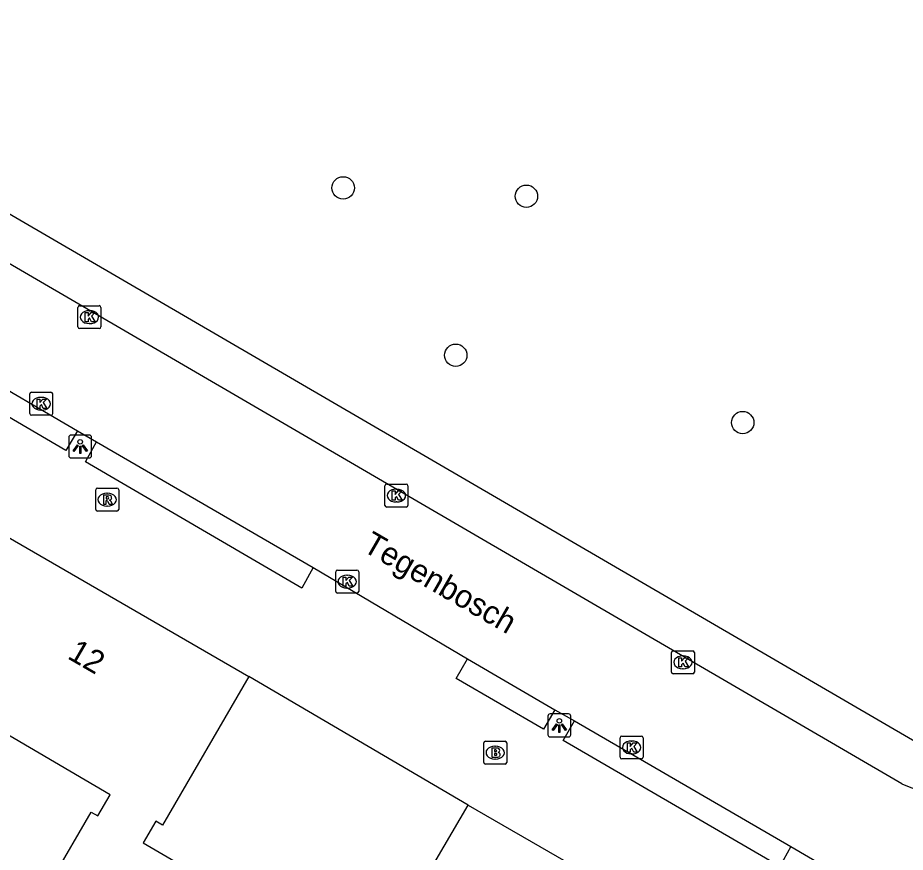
# Model space of a CAD drawing. Extents: x 156502 to 159074, y 384229 to 386094.
# Drawn here: x 157135.98 to 157174.65, y 385827.46 to 385863.84 of the extents above; entities that cross this region are included whole.
import ezdxf

# ---------------------------------------------------------------- set-up
doc = ezdxf.new("R2010")
doc.units = 0
for name, color, linetype in [('IMGEO_Boom', 7, 'Continuous'), ('IMGEO_Brandkraan', 7, 'Continuous'), ('IMGEO_Hek', 7, 'Continuous'), ('IMGEO_Kolk', 7, 'Continuous'), ('IMGEO_Lichtpunt', 7, 'Continuous'), ('IMGEO_Openbare_ruimte_label', 7, 'Continuous'), ('IMGEO_Pand', 7, 'Continuous'), ('IMGEO_Pand_nummerreeks', 7, 'Continuous'), ('IMGEO_Parkeervlak_open', 7, 'Continuous'), ('IMGEO_Rijbaan_lokaal_open', 7, 'Continuous'), ('IMGEO_Rioolput', 7, 'Continuous'), ('IMGEO_Voetpad_open', 7, 'Continuous')]:
    doc.layers.add(name, color=color, linetype=linetype)

msp = doc.modelspace()

# ---------------------------------------------------------------- linework, layer by layer
at = {"layer": 'IMGEO_Boom'}
for centre in [(157150.156, 385856.417), (157158.138, 385856.053), (157155.059, 385849.123), (157167.563, 385846.188)]:
    msp.add_circle(centre, 0.489, dxfattribs=at)
at = {"layer": 'IMGEO_Brandkraan'}
for p, q in [((157156.28, 385831.377), (157156.28, 385832.229)), ((157156.355, 385832.303), (157157.207, 385832.303)), ((157156.768, 385832.083), (157156.793, 385832.083)), ((157157.281, 385832.229), (157157.281, 385831.377)), ((157157.207, 385831.303), (157156.355, 385831.303)), ((157156.791, 385831.523), (157156.766, 385831.523))]:
    msp.add_line(p, q, dxfattribs=at)
for points in [[(157156.28, 385831.377), (157156.28, 385832.229)], [(157156.355, 385832.303), (157157.207, 385832.303)], [(157156.628, 385832.003), (157156.628, 385831.603), (157156.841, 385831.603)], [(157156.859, 385832.003), (157156.628, 385832.003)], [(157157.281, 385832.229), (157157.281, 385831.377)], [(157156.807, 385831.922), (157156.753, 385831.922), (157156.753, 385831.846)], [(157156.753, 385831.846), (157156.806, 385831.846)], [(157156.815, 385831.77), (157156.753, 385831.77), (157156.753, 385831.689)], [(157156.753, 385831.689), (157156.815, 385831.689)], [(157157.207, 385831.303), (157156.355, 385831.303)]]:
    msp.add_lwpolyline(points, dxfattribs=at)
for centre, radius, start, end in [((157156.357, 385832.227), 0.0765, 91.552, 178.448), ((157156.357, 385832.227), 0.0765, 91.552, 178.448), ((157156.863, 385831.858), 0.145, 59.4692, 91.5367), ((157157.205, 385832.227), 0.0765, 1.552, 88.448), ((157157.205, 385832.227), 0.0765, 1.552, 88.448), ((157156.808, 385831.884), 0.0379, 267.8285, 90.9355), ((157156.816, 385831.729), 0.0404, 269.8759, 90.5077), ((157156.847, 385831.854), 0.251, 268.6676, 293.5347), ((157156.888, 385831.905), 0.0922, 285.5137, 58.1501), ((157156.893, 385831.713), 0.105, 301.3115, 78.989), ((157156.357, 385831.379), 0.0765, 181.552, 268.448), ((157156.357, 385831.379), 0.0765, 181.552, 268.448), ((157157.205, 385831.379), 0.0765, 271.552, 358.448), ((157157.205, 385831.379), 0.0765, 271.552, 358.448)]:
    msp.add_arc(centre, radius, start, end, dxfattribs=at)
for centre, major_axis, ratio, start_param, end_param in [((157156.767, 385831.803), (-0.387, 0.002), 0.722429, 4.712389, 7.853982), ((157156.792, 385831.803), (-0.39, 0.002), 0.717154, 1.570796, 4.712389)]:
    msp.add_ellipse(centre, major_axis=major_axis, ratio=ratio, start_param=start_param, end_param=end_param, dxfattribs=at)
at = {"layer": 'IMGEO_Hek'}
msp.add_lwpolyline([(157155.595, 385829.52), (157146.045, 385835.121)], dxfattribs=at)
at = {"layer": 'IMGEO_Kolk'}
for p, q in [((157138.599, 385850.359), (157138.599, 385851.211)), ((157138.674, 385851.285), (157139.526, 385851.285)), ((157139.087, 385851.065), (157139.112, 385851.065)), ((157139.6, 385851.211), (157139.6, 385850.359)), ((157139.526, 385850.285), (157138.674, 385850.285)), ((157139.11, 385850.505), (157139.085, 385850.505)), ((157136.572, 385847.51), (157137.424, 385847.51)), ((157136.497, 385846.584), (157136.497, 385847.436)), ((157136.985, 385847.29), (157137.01, 385847.29)), ((157137.498, 385847.436), (157137.498, 385846.584)), ((157137.008, 385846.73), (157136.983, 385846.73)), ((157137.424, 385846.51), (157136.572, 385846.51)), ((157151.976, 385842.582), (157151.976, 385843.434)), ((157152.051, 385843.508), (157152.903, 385843.508)), ((157152.464, 385843.288), (157152.489, 385843.288)), ((157152.977, 385843.434), (157152.977, 385842.582)), ((157152.903, 385842.508), (157152.051, 385842.508)), ((157152.487, 385842.728), (157152.462, 385842.728)), ((157149.906, 385839.757), (157150.758, 385839.757)), ((157149.831, 385838.831), (157149.831, 385839.683)), ((157150.319, 385839.537), (157150.344, 385839.537)), ((157150.832, 385839.683), (157150.832, 385838.831)), ((157150.342, 385838.977), (157150.317, 385838.977)), ((157150.758, 385838.757), (157149.906, 385838.757)), ((157164.46, 385835.314), (157164.46, 385836.166)), ((157164.535, 385836.24), (157165.387, 385836.24)), ((157164.948, 385836.02), (157164.973, 385836.02)), ((157165.461, 385836.166), (157165.461, 385835.314)), ((157165.387, 385835.24), (157164.535, 385835.24)), ((157164.971, 385835.46), (157164.946, 385835.46)), ((157162.223, 385831.602), (157162.223, 385832.454)), ((157162.298, 385832.528), (157163.15, 385832.528)), ((157163.224, 385832.454), (157163.224, 385831.602)), ((157162.711, 385832.308), (157162.736, 385832.308)), ((157162.734, 385831.748), (157162.709, 385831.748)), ((157163.15, 385831.528), (157162.298, 385831.528))]:
    msp.add_line(p, q, dxfattribs=at)
for points in [[(157138.599, 385850.359), (157138.599, 385851.211)], [(157138.674, 385851.285), (157139.526, 385851.285)], [(157138.92, 385850.985), (157139.043, 385850.985), (157139.043, 385850.834), (157139.173, 385850.985), (157139.337, 385850.985), (157139.191, 385850.834), (157139.344, 385850.585), (157139.192, 385850.585), (157139.107, 385850.749), (157139.043, 385850.682), (157139.043, 385850.585), (157138.92, 385850.585), (157138.92, 385850.985)], [(157139.6, 385851.211), (157139.6, 385850.359)], [(157139.526, 385850.285), (157138.674, 385850.285)], [(157136.572, 385847.51), (157137.424, 385847.51)], [(157136.497, 385846.584), (157136.497, 385847.436)], [(157136.818, 385847.21), (157136.941, 385847.21), (157136.941, 385847.059), (157137.071, 385847.21), (157137.235, 385847.21), (157137.089, 385847.059), (157137.242, 385846.81), (157137.09, 385846.81), (157137.005, 385846.974), (157136.941, 385846.907), (157136.941, 385846.81), (157136.818, 385846.81), (157136.818, 385847.21)], [(157137.498, 385847.436), (157137.498, 385846.584)], [(157137.424, 385846.51), (157136.572, 385846.51)], [(157151.976, 385842.582), (157151.976, 385843.434)], [(157152.051, 385843.508), (157152.903, 385843.508)], [(157152.977, 385843.434), (157152.977, 385842.582)], [(157152.297, 385843.208), (157152.42, 385843.208), (157152.42, 385843.057), (157152.55, 385843.208), (157152.714, 385843.208), (157152.568, 385843.057), (157152.721, 385842.808), (157152.569, 385842.808), (157152.484, 385842.972), (157152.42, 385842.905), (157152.42, 385842.808), (157152.297, 385842.808), (157152.297, 385843.208)], [(157152.903, 385842.508), (157152.051, 385842.508)], [(157149.906, 385839.757), (157150.758, 385839.757)], [(157149.831, 385838.831), (157149.831, 385839.683)], [(157150.152, 385839.457), (157150.275, 385839.457), (157150.275, 385839.306), (157150.405, 385839.457), (157150.569, 385839.457), (157150.423, 385839.306), (157150.576, 385839.057), (157150.424, 385839.057), (157150.339, 385839.221), (157150.275, 385839.154), (157150.275, 385839.057), (157150.152, 385839.057), (157150.152, 385839.457)], [(157150.832, 385839.683), (157150.832, 385838.831)], [(157150.758, 385838.757), (157149.906, 385838.757)], [(157164.46, 385835.314), (157164.46, 385836.166)], [(157164.535, 385836.24), (157165.387, 385836.24)], [(157164.781, 385835.94), (157164.904, 385835.94), (157164.904, 385835.789), (157165.034, 385835.94), (157165.198, 385835.94), (157165.052, 385835.789), (157165.205, 385835.54), (157165.053, 385835.54), (157164.968, 385835.704), (157164.904, 385835.637), (157164.904, 385835.54), (157164.781, 385835.54), (157164.781, 385835.94)], [(157165.461, 385836.166), (157165.461, 385835.314)], [(157165.387, 385835.24), (157164.535, 385835.24)], [(157162.223, 385831.602), (157162.223, 385832.454)], [(157162.298, 385832.528), (157163.15, 385832.528)], [(157163.224, 385832.454), (157163.224, 385831.602)], [(157162.544, 385832.228), (157162.667, 385832.228), (157162.667, 385832.077), (157162.797, 385832.228), (157162.961, 385832.228), (157162.815, 385832.077), (157162.968, 385831.828), (157162.816, 385831.828), (157162.731, 385831.992), (157162.667, 385831.925), (157162.667, 385831.828), (157162.544, 385831.828), (157162.544, 385832.228)], [(157163.15, 385831.528), (157162.298, 385831.528)]]:
    msp.add_lwpolyline(points, dxfattribs=at)
for centre, start, end in [((157138.676, 385851.209), 91.552, 178.448), ((157138.676, 385851.209), 91.552, 178.448), ((157139.524, 385851.209), 1.552, 88.448), ((157139.524, 385851.209), 1.552, 88.448), ((157138.676, 385850.361), 181.552, 268.448), ((157138.676, 385850.361), 181.552, 268.448), ((157139.524, 385850.361), 271.552, 358.448), ((157139.524, 385850.361), 271.552, 358.448), ((157136.574, 385847.434), 91.552, 178.448), ((157136.574, 385847.434), 91.552, 178.448), ((157137.422, 385847.434), 1.552, 88.448), ((157137.422, 385847.434), 1.552, 88.448), ((157136.574, 385846.586), 181.552, 268.448), ((157136.574, 385846.586), 181.552, 268.448), ((157137.422, 385846.586), 271.552, 358.448), ((157137.422, 385846.586), 271.552, 358.448), ((157152.053, 385843.432), 91.552, 178.448), ((157152.053, 385843.432), 91.552, 178.448), ((157152.901, 385843.432), 1.552, 88.448), ((157152.901, 385843.432), 1.552, 88.448), ((157152.053, 385842.584), 181.552, 268.448), ((157152.053, 385842.584), 181.552, 268.448), ((157152.901, 385842.584), 271.552, 358.448), ((157152.901, 385842.584), 271.552, 358.448), ((157149.908, 385839.681), 91.552, 178.448), ((157149.908, 385839.681), 91.552, 178.448), ((157150.756, 385839.681), 1.552, 88.448), ((157150.756, 385839.681), 1.552, 88.448), ((157149.908, 385838.833), 181.552, 268.448), ((157149.908, 385838.833), 181.552, 268.448), ((157150.756, 385838.833), 271.552, 358.448), ((157150.756, 385838.833), 271.552, 358.448), ((157164.537, 385836.164), 91.552, 178.448), ((157164.537, 385836.164), 91.552, 178.448), ((157165.385, 385836.164), 1.552, 88.448), ((157165.385, 385836.164), 1.552, 88.448), ((157164.537, 385835.316), 181.552, 268.448), ((157164.537, 385835.316), 181.552, 268.448), ((157165.385, 385835.316), 271.552, 358.448), ((157165.385, 385835.316), 271.552, 358.448), ((157162.3, 385832.452), 91.552, 178.448), ((157162.3, 385832.452), 91.552, 178.448), ((157163.148, 385832.452), 1.552, 88.448), ((157163.148, 385832.452), 1.552, 88.448), ((157162.3, 385831.604), 181.552, 268.448), ((157162.3, 385831.604), 181.552, 268.448), ((157163.148, 385831.604), 271.552, 358.448), ((157163.148, 385831.604), 271.552, 358.448)]:
    msp.add_arc(centre, 0.0765, start, end, dxfattribs=at)
for centre, major_axis, ratio, start_param, end_param in [((157139.086, 385850.785), (-0.387, 0.002), 0.722429, 4.712389, 7.853982), ((157139.111, 385850.785), (-0.39, 0.002), 0.717154, 1.570796, 4.712389), ((157136.984, 385847.01), (-0.387, 0.002), 0.722429, 4.712389, 7.853982), ((157137.009, 385847.01), (-0.39, 0.002), 0.717154, 1.570796, 4.712389), ((157152.463, 385843.008), (-0.387, 0.002), 0.722429, 4.712389, 7.853982), ((157152.488, 385843.008), (-0.39, 0.002), 0.717154, 1.570796, 4.712389), ((157150.318, 385839.257), (-0.387, 0.002), 0.722429, 4.712389, 7.853982), ((157150.343, 385839.257), (-0.39, 0.002), 0.717154, 1.570796, 4.712389), ((157164.947, 385835.74), (-0.387, 0.002), 0.722429, 4.712389, 7.853982), ((157164.972, 385835.74), (-0.39, 0.002), 0.717154, 1.570796, 4.712389), ((157162.71, 385832.028), (-0.387, 0.002), 0.722429, 4.712389, 7.853982), ((157162.735, 385832.028), (-0.39, 0.002), 0.717154, 1.570796, 4.712389)]:
    msp.add_ellipse(centre, major_axis=major_axis, ratio=ratio, start_param=start_param, end_param=end_param, dxfattribs=at)
at = {"layer": 'IMGEO_Lichtpunt'}
for p, q in [((157138.199, 385845.55), (157138.199, 385844.743)), ((157138.199, 385845.55), (157138.199, 385844.743)), ((157139.101, 385845.645), (157138.293, 385845.645)), ((157139.101, 385845.645), (157138.293, 385845.645)), ((157139.195, 385844.743), (157139.195, 385845.55)), ((157139.195, 385844.743), (157139.195, 385845.55)), ((157138.293, 385844.649), (157139.101, 385844.649)), ((157138.293, 385844.649), (157139.101, 385844.649)), ((157159.077, 385833.393), (157159.077, 385832.586)), ((157159.077, 385833.393), (157159.077, 385832.586)), ((157159.979, 385833.488), (157159.171, 385833.488)), ((157159.979, 385833.488), (157159.171, 385833.488)), ((157160.073, 385832.586), (157160.073, 385833.393)), ((157160.073, 385832.586), (157160.073, 385833.393)), ((157159.171, 385832.492), (157159.979, 385832.492)), ((157159.171, 385832.492), (157159.979, 385832.492))]:
    msp.add_line(p, q, dxfattribs=at)
for points in [[(157138.573, 385845.214), (157138.612, 385845.186), (157138.424, 385844.924), (157138.386, 385844.951), (157138.573, 385845.214)], [(157138.675, 385845.166), (157138.722, 385845.166), (157138.722, 385844.844), (157138.675, 385844.844), (157138.675, 385845.166)], [(157138.785, 385845.186), (157138.823, 385845.213), (157139.01, 385844.951), (157138.971, 385844.923), (157138.785, 385845.186)], [(157159.451, 385833.057), (157159.49, 385833.029), (157159.302, 385832.767), (157159.264, 385832.794), (157159.451, 385833.057)], [(157159.553, 385833.009), (157159.6, 385833.009), (157159.6, 385832.687), (157159.553, 385832.687), (157159.553, 385833.009)], [(157159.663, 385833.029), (157159.701, 385833.056), (157159.888, 385832.794), (157159.849, 385832.766), (157159.663, 385833.029)]]:
    msp.add_lwpolyline(points, dxfattribs=at)
for centre in [(157138.698, 385845.348), (157159.576, 385833.191)]:
    msp.add_circle(centre, 0.0994, dxfattribs=at)
for centre, start, end in [((157138.293, 385845.55), 90, 180), ((157138.293, 385845.55), 90, 180), ((157139.101, 385845.55), 0, 90), ((157139.101, 385845.55), 0, 90), ((157138.293, 385844.743), 180, 270), ((157138.293, 385844.743), 180, 270), ((157139.101, 385844.743), 270, 0), ((157139.101, 385844.743), 270, 360), ((157159.171, 385833.393), 90, 180), ((157159.171, 385833.393), 90, 180), ((157159.979, 385833.393), 0, 90), ((157159.979, 385833.393), 0, 90), ((157159.171, 385832.586), 180, 270), ((157159.171, 385832.586), 180, 270), ((157159.979, 385832.586), 270, 0), ((157159.979, 385832.586), 270, 360)]:
    msp.add_arc(centre, 0.0946, start, end, dxfattribs=at)
at = {"layer": 'IMGEO_Pand'}
for points in [[(157146.045, 385835.121), (157142.29, 385828.637), (157141.989, 385828.812), (157141.44, 385827.871), (157146.528, 385824.906), (157141.519, 385816.264), (157134.144, 385820.573), (157139.17, 385829.213), (157139.464, 385829.042), (157140.002, 385829.967), (157130.951, 385835.263), (157134.715, 385841.68)], [(157134.715, 385841.68), (157146.045, 385835.121)], [(157159.85, 385827.054), (157159.093, 385825.747), (157166.175, 385821.643), (157162.465, 385815.184), (157162.231, 385815.319), (157161.733, 385814.451), (157166.702, 385811.491), (157163.329, 385805.74), (157155.962, 385810.061), (157159.324, 385815.821), (157159.704, 385815.599), (157160.195, 385816.468), (157151.075, 385821.767), (157155.595, 385829.52)], [(157155.595, 385829.52), (157159.85, 385827.054)]]:
    msp.add_lwpolyline(points, dxfattribs=at)
at = {"layer": 'IMGEO_Parkeervlak_open'}
msp.add_lwpolyline([(157175.135, 385832.241), (157120.919, 385863.835)], dxfattribs=at)
at = {"layer": 'IMGEO_Rijbaan_lokaal_open'}
for points in [[(157174.491, 385830.448), (157119.853, 385862.285)], [(157133.897, 385848.562), (157138.584, 385845.831)], [(157138.584, 385845.831), (157139.408, 385845.347)], [(157139.408, 385845.347), (157148.842, 385839.867)], [(157148.842, 385839.867), (157155.57, 385835.897)], [(157155.57, 385835.897), (157159.377, 385833.674)], [(157159.377, 385833.674), (157160.239, 385833.196)], [(157160.239, 385833.196), (157169.662, 385827.706)], [(157169.662, 385827.706), (157174.449, 385824.915)]]:
    msp.add_lwpolyline(points, dxfattribs=at)
msp.add_arc((157176.428, 385834.448), 4.444, 244.161, 329.3159, dxfattribs=at)
at = {"layer": 'IMGEO_Rioolput'}
for p, q in [((157139.373, 385842.405), (157139.373, 385843.257)), ((157139.448, 385843.331), (157140.3, 385843.331)), ((157140.374, 385843.257), (157140.374, 385842.405)), ((157139.861, 385843.111), (157139.886, 385843.111)), ((157139.884, 385842.551), (157139.859, 385842.551)), ((157140.3, 385842.331), (157139.448, 385842.331))]:
    msp.add_line(p, q, dxfattribs=at)
for points in [[(157139.373, 385842.405), (157139.373, 385843.257)], [(157139.448, 385843.331), (157140.3, 385843.331)], [(157140.374, 385843.257), (157140.374, 385842.405)], [(157139.962, 385843.029), (157139.71, 385843.031), (157139.71, 385842.631)], [(157139.888, 385842.95), (157139.834, 385842.95), (157139.834, 385842.869)], [(157139.834, 385842.869), (157139.886, 385842.869)], [(157139.71, 385842.631), (157139.834, 385842.631), (157139.834, 385842.793), (157139.845, 385842.793)], [(157139.892, 385842.764), (157139.963, 385842.631), (157140.103, 385842.631), (157140.038, 385842.757)], [(157140.3, 385842.331), (157139.448, 385842.331)]]:
    msp.add_lwpolyline(points, dxfattribs=at)
for centre, radius, start, end in [((157139.45, 385843.255), 0.0765, 91.552, 178.448), ((157139.45, 385843.255), 0.0765, 91.552, 178.448), ((157140.298, 385843.255), 0.0765, 1.552, 88.448), ((157140.298, 385843.255), 0.0765, 1.552, 88.448), ((157139.87, 385843.058), 0.19, 274.7715, 282.9687), ((157139.894, 385842.854), 0.0964, 77.0061, 93.1865), ((157139.908, 385842.911), 0.0378, 276.6634, 79.6772), ((157139.961, 385842.919), 0.109, 350.3612, 89.416), ((157139.959, 385842.919), 0.112, 277.5842, 350.9817), ((157139.844, 385842.74), 0.0533, 26.0293, 88.6989), ((157139.943, 385842.704), 0.108, 29.5134, 73.7905), ((157139.45, 385842.407), 0.0765, 181.552, 268.448), ((157139.45, 385842.407), 0.0765, 181.552, 268.448), ((157140.298, 385842.407), 0.0765, 271.552, 358.448), ((157140.298, 385842.407), 0.0765, 271.552, 358.448)]:
    msp.add_arc(centre, radius, start, end, dxfattribs=at)
for centre, major_axis, ratio, start_param, end_param in [((157139.86, 385842.831), (-0.387, 0.002), 0.722429, 4.712389, 7.853982), ((157139.885, 385842.831), (-0.39, 0.002), 0.717154, 1.570796, 4.712389)]:
    msp.add_ellipse(centre, major_axis=major_axis, ratio=ratio, start_param=start_param, end_param=end_param, dxfattribs=at)
at = {"layer": 'IMGEO_Voetpad_open'}
for points in [[(157138.584, 385845.831), (157138.076, 385844.975), (157133.418, 385847.696), (157133.897, 385848.562)], [(157148.842, 385839.867), (157148.354, 385838.978), (157138.927, 385844.474), (157139.408, 385845.347)], [(157159.377, 385833.674), (157158.886, 385832.827), (157155.076, 385835.039), (157155.57, 385835.897)], [(157155.595, 385829.52), (157146.045, 385835.121)], [(157169.662, 385827.706), (157169.178, 385826.84), (157159.74, 385832.335), (157160.239, 385833.196)]]:
    msp.add_lwpolyline(points, dxfattribs=at)

# ---------------------------------------------------------------- texts
at = {"layer": 'IMGEO_Openbare_ruimte_label'}
msp.add_text('Tegenbosch', height=1, rotation=330.0489, dxfattribs=at).set_placement((157150.949, 385840.623))
at = {"layer": 'IMGEO_Pand_nummerreeks'}
msp.add_text('12', height=1, rotation=329.9336, dxfattribs=at).set_placement((157138.097, 385835.932))

doc.saveas('drawing.dxf')
